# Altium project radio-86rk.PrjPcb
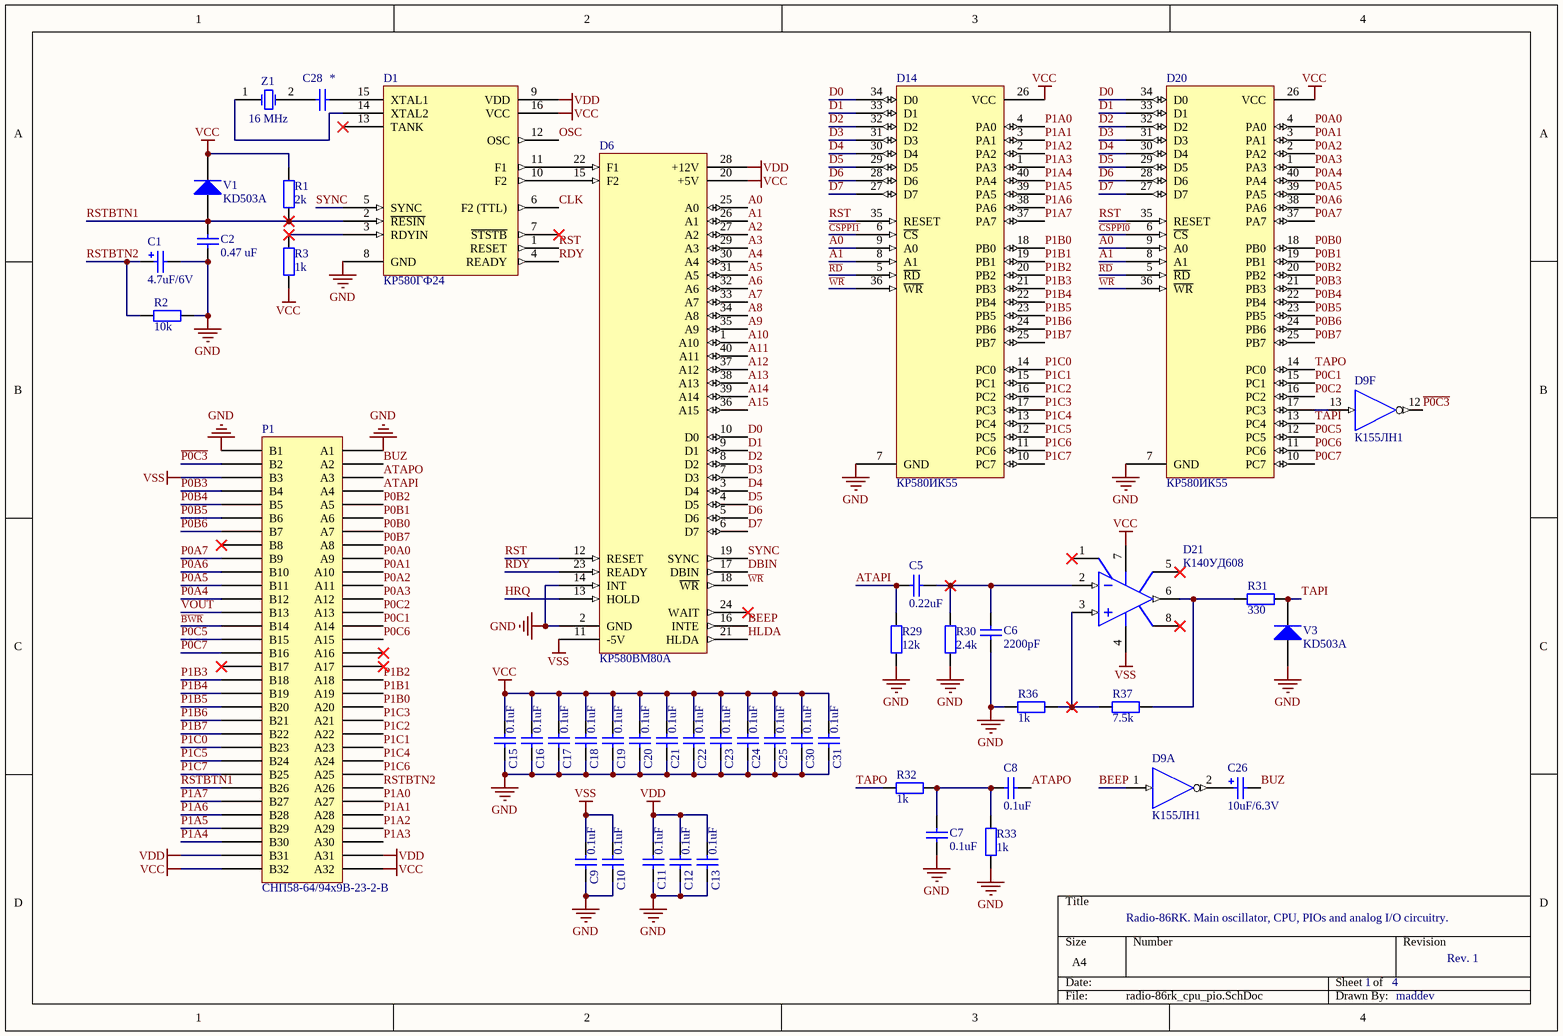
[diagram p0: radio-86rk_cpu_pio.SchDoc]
4 sheets, 104 parts. Net scope: global (net labels, ports and power ports of the same name join across sheets).
Board file: radio-86rk.PcbDoc
Sheets:
  radio-86rk_cpu_pio.SchDoc
  radio-86rk_control.SchDoc
  radio-86rk_rom_ram.SchDoc
  radio-86rk_dma_crt.SchDoc

## Sheet radio-86rk_cpu_pio.SchDoc: Radio-86RK. Main oscillator, CPU, PIOs and analog I/O circuitry.
size A4; DrawnBy: maddev; Revision: Rev. 1; SheetNumber: 1; SheetTotal: 4

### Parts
C1  4.7uF/6V  [CAPPR2.5-6.3x11]
C2  0.47 uF  [CAPR5.08-5.1x2.5]
C5  0.22uF  [CAPR5.08-5.1x2.5]
C6  2200pF  [CAPR5.08-5.1x2.5]
C7  0.1uF  [CAPR5.08-5.1x2.5]
C8  0.1uF  [CAPR5.08-5.1x2.5]
C9  0.1uF  [CAPR5.08-5.1x2.5]
C10  0.1uF  [CAPR5.08-5.1x2.5]
C11  0.1uF  [CAPR5.08-5.1x2.5]
C12  0.1uF  [CAPR5.08-5.1x2.5]
C13  0.1uF  [CAPR5.08-5.1x2.5]
C15  0.1uF  [CAPR5.08-5.1x2.5]
C16  0.1uF  [CAPR5.08-5.1x2.5]
C17  0.1uF  [CAPR5.08-5.1x2.5]
C18  0.1uF  [CAPR5.08-5.1x2.5]
C19  0.1uF  [CAPR5.08-5.1x2.5]
C20  0.1uF  [CAPR5.08-5.1x2.5]
C21  0.1uF  [CAPR5.08-5.1x2.5]
C22  0.1uF  [CAPR5.08-5.1x2.5]
C23  0.1uF  [CAPR5.08-5.1x2.5]
C24  0.1uF  [CAPR5.08-5.1x2.5]
C25  0.1uF  [CAPR5.08-5.1x2.5]
C26  10uF/6.3V  [CAPPR2.5-6.3x11]
C28  *  [CAPR5.08-5.1x2.5]
C30  0.1uF  [CAPR5.08-5.1x2.5]
C31  0.1uF  [CAPR5.08-5.1x2.5]
D1  КР580ГФ24  [DIP16M]
D6  КР580ВМ80А  [DIP40M]
D9  К155ЛН1  [DIP14M]  (parts A,F of 6)
D14  КР580ИК55  [DIP40M]
D20  КР580ИК55  [DIP40M]
D21  К140УД608  [DIP8M]
P1  СНП58-64/94x9В-23-2-В  [snp58]
R1  2k  [AXIAL-0.4]
R2  10k  [AXIAL-0.4]
R3  1k  [AXIAL-0.4]
R29  12k  [AXIAL-0.4]
R30  2.4k  [AXIAL-0.4]
R31  330  [AXIAL-0.4]
R32  1k  [AXIAL-0.4]
R33  1k  [AXIAL-0.4]
R36  1k  [AXIAL-0.4]
R37  7.5k  [AXIAL-0.4]
V1  KD503A  [DO-35A]
V3  KD503A  [DO-35A]
Z1  16 MHz  [HC-49U]

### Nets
GND: C1.2 C2.1 C6.1 C7.1 C9.1 C10.1 C11.1 C12.1 C13.1 C15.1 C16.1 C17.1 C18.1 C19.1 C20.1 C21.1 C22.1 C23.1 C24.1 C25.1 C30.1 C31.1 D1.8(GND) D6.2(GND) D6.14(INT) D9.7(GND) D14.7(GND) D20.7(GND) P1.A1 P1.B1 R2.1 R29.1 R30.1 R33.1 R36.2 V3.1(A)
VCC: C15.2 C16.2 C17.2 C18.2 C19.2 C20.2 C21.2 C22.2 C23.2 C24.2 C25.2 C30.2 C31.2 D1.16(VCC) D6.20(+5V) D9.14(VCC) D14.26(VCC) D20.26(VCC) D21.7(V+) P1.A32 P1.B32 R1.2 R3.1 V1.2(K)
VDD: C11.2 C12.2 C13.2 D1.9(VDD) D6.28(+12V) P1.A31 P1.B31
VSS: C9.2 C10.2 D6.11(-5V) D21.4(V-) P1.B3
A0: D6.25(A0) D14.9(A0) D20.9(A0)
A1: D6.26(A1) D14.8(A1) D20.8(A1)
A2: D6.27(A2)
A3: D6.29(A3)
A4: D6.30(A4)
A5: D6.31(A5)
A6: D6.32(A6)
A7: D6.33(A7)
A8: D6.34(A8)
A9: D6.35(A9)
A10: D6.1(A10)
A11: D6.40(A11)
A12: D6.37(A12)
A13: D6.38(A13)
A14: D6.39(A14)
A15: D6.36(A15)
ATAPI: C5.2 P1.A4 R29.2
ATAPO: C8.1 P1.A3
~{BWR}: P1.B14
BEEP: D6.16(INTE) D9.1(A)
BUZ: C26.2 P1.A2
~{CSPPI0}: D20.6(~{CS})
~{CSPPI1}: D14.6(~{CS})
CLK: D1.6(F2_(TTL))
D0: D6.10(D0) D14.34(D0) D20.34(D0)
D1: D6.9(D1) D14.33(D1) D20.33(D1)
D2: D6.8(D2) D14.32(D2) D20.32(D2)
D3: D6.7(D3) D14.31(D3) D20.31(D3)
D4: D6.3(D4) D14.30(D4) D20.30(D4)
D5: D6.4(D5) D14.29(D5) D20.29(D5)
D6: D6.5(D6) D14.28(D6) D20.28(D6)
D7: D6.6(D7) D14.27(D7) D20.27(D7)
DBIN: D6.17(DBIN)
HLDA: D6.21(HLDA)
HRQ: D6.13(HOLD)
OSC: D1.12(OSC)
P0A0: D20.4(PA0) P1.A9
P0A1: D20.3(PA1) P1.A10
P0A2: D20.2(PA2) P1.A11
P0A3: D20.1(PA3) P1.A12
P0A4: D20.40(PA4) P1.B12
P0A5: D20.39(PA5) P1.B11
P0A6: D20.38(PA6) P1.B10
P0A7: D20.37(PA7) P1.B9
P0B0: D20.18(PB0) P1.A7
P0B1: D20.19(PB1) P1.A6
P0B2: D20.20(PB2) P1.A5
P0B3: D20.21(PB3) P1.B4
P0B4: D20.22(PB4) P1.B5
P0B5: D20.23(PB5) P1.B6
P0B6: D20.24(PB6) P1.B7
P0B7: D20.25(PB7) P1.A8
P0C1: D20.15(PC1) P1.A14
P0C2: D20.16(PC2) P1.A13
P0C5: D20.12(PC5) P1.B15
P0C6: D20.11(PC6) P1.A15
P0C7: D20.10(PC7) P1.B16
P1A0: D14.4(PA0) P1.A27
P1A1: D14.3(PA1) P1.A28
P1A2: D14.2(PA2) P1.A29
P1A3: D14.1(PA3) P1.A30
P1A4: D14.40(PA4) P1.B30
P1A5: D14.39(PA5) P1.B29
P1A6: D14.38(PA6) P1.B28
P1A7: D14.37(PA7) P1.B27
P1B0: D14.18(PB0) P1.A20
P1B1: D14.19(PB1) P1.A19
P1B2: D14.20(PB2) P1.A18
P1B3: D14.21(PB3) P1.B18
P1B4: D14.22(PB4) P1.B19
P1B5: D14.23(PB5) P1.B20
P1B6: D14.24(PB6) P1.B21
P1B7: D14.25(PB7) P1.B22
P1C0: D14.14(PC0) P1.B23
P1C1: D14.15(PC1) P1.A23
P1C2: D14.16(PC2) P1.A22
P1C3: D14.17(PC3) P1.A21
P1C4: D14.13(PC4) P1.A24
P1C5: D14.12(PC5) P1.B24
P1C6: D14.11(PC6) P1.A25
P1C7: D14.10(PC7) P1.B25
~{P0C3}: D9.12(Y) P1.B2
~{RD}: D14.5(~{RD}) D20.5(~{RD})
RDY: D1.4(READY) D6.23(READY)
RST: D1.1(RESET) D6.12(RESET) D14.35(RESET) D20.35(RESET)
RSTBTN1: C2.2 D1.2(~{RESIN}) P1.B26 R1.1 V1.1(A)
RSTBTN2: C1.1 P1.A26 R2.2
SYNC: D1.5(SYNC) D6.19(SYNC)
TAPI: D20.13(PC4) R31.2 V3.2(K)
TAPO: D20.14(PC0) R32.1
VOUT: P1.B13
~{WR}: D6.18(~{WR}) D14.36(~{WR}) D20.36(~{WR})
NetC5_1: C5.1 C6.2 D21.2(IN-) R30.2
NetC7_2: C7.2 C8.2 R32.2 R33.2
NetC26_1: C26.1 D9.2(Y)
NetC28_1: C28.1 D1.15(XTAL1)
NetC28_2: C28.2 Z1.2(OSC2)
NetD1_3: D1.3(RDYIN) R3.2
NetD1_10: D1.10(F2) D6.15(F2)
NetD1_11: D1.11(F1) D6.22(F1)
NetD1_14: D1.14(XTAL2) Z1.1(OSC1)
NetD9_13: D9.13(A) D20.17(PC3)
NetD21_3: D21.3(IN+) R36.1 R37.2
NetD21_6: D21.6(OUT) R31.1 R37.1

Not connected (* = marked no-connect by the designer): D1 7(~{STSTB})* 13(TANK)*; D6 24(WAIT)*; D21 1(OS_NULL)* 5(OS_NULL)* 8(NC)*; P1 A16* A17* B8* B17*

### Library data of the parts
C1 = Cap Pol2: Polarized Capacitor (Axial); AltValue: 10uF/6.3V
C2 = Cap: Capacitor; AltValue: 1uF
C5-C13 C15-C25 C30 C31 = Cap: Capacitor; Value: 100pF
C26 = Cap Pol2: Polarized Capacitor (Axial); Value: 100pF
C28 = Cap: Capacitor; AltValue: JUMPER
D1 = КР580ГФ24: Clock generator and driver for 8080A CPU
D6 = КР580ВМ80А: 8-bit N-channel microprocessor
D9 = SN7404N: Hex Inverter
D14 D20 = КР580ИК55: Programmable peripheral interface
D21 = MC1456P1: High-Performance Operational Amplifier
R1 = Res2: Resistor; AltValue: 1k
R2 R29-R31 R37 = Res2: Resistor; Value: 1K
R3 R32 R33 R36 = Res2: Resistor
V1 V3 = Diode 1N4149: Computer Diode
Z1 = XTAL: Crystal Oscillator

## Sheet radio-86rk_control.SchDoc: Radio-86RK. Address decoding and DRAM control.
size A4; DrawnBy: maddev; Revision: Rev. 1; SheetNumber: 2; SheetTotal: 4
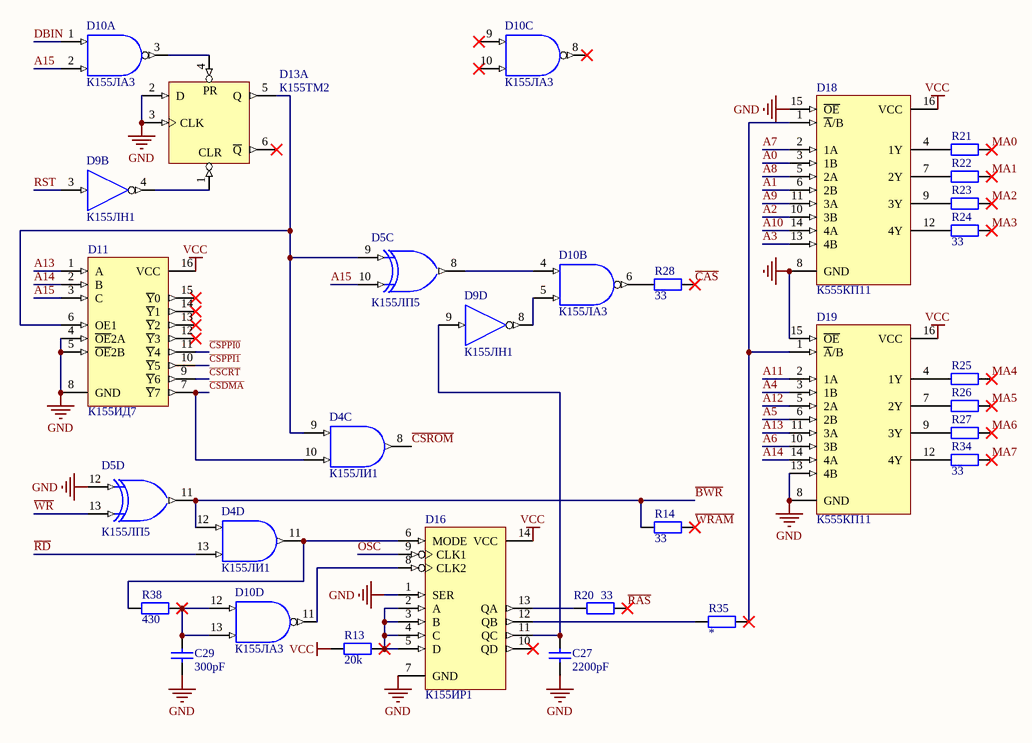
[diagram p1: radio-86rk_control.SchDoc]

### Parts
C27  2200pF  [CAPR5.08-5.1x2.5]
C29  300pF  [CAPR5.08-5.1x2.5]
D4  К155ЛИ1  [DIP14M]  (parts C,D of 4)
D5  К155ЛП5  [DIP14M]  (parts C,D of 4)
D9  К155ЛН1  [DIP14M]  (parts B,D of 6)
D10  К155ЛА3  [DIP14M]  (parts A,B,C,D of 4)
D11  К155ИД7  [DIP16M]
D13  К155ТМ2  [DIP14M]  (part A of 2)
D16  К155ИР1  [DIP14M]
D18  К555КП11  [DIP16M]
D19  К555КП11  [DIP16M]
R13  20k  [AXIAL-0.4]
R14  33  [AXIAL-0.4]
R20  33  [AXIAL-0.4]
R21  33  [AXIAL-0.4]  (value not drawn)
R22  33  [AXIAL-0.4]  (value not drawn)
R23  33  [AXIAL-0.4]  (value not drawn)
R24  33  [AXIAL-0.4]
R25  33  [AXIAL-0.4]  (value not drawn)
R26  33  [AXIAL-0.4]  (value not drawn)
R27  33  [AXIAL-0.4]  (value not drawn)
R28  33  [AXIAL-0.4]
R34  33  [AXIAL-0.4]
R35  *  [AXIAL-0.4]
R38  430  [AXIAL-0.4]

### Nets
GND: C27.2 C29.2 D4.7(GND) D5.7(GND) D5.12(A) D9.7(GND) D10.7(GND) D11.4(~{OE}2A) D11.5(~{OE}2B) D11.8(GND) D13.2(D) D13.3(CLK) D13.7(GND) D16.1(SER) D16.7(GND) D18.8(GND) D18.15(~{OE}) D19.8(GND) D19.13(4B) D19.15(~{OE})
VCC: D4.14(VCC) D5.14(VCC) D9.14(VCC) D10.14(VCC) D11.16(VCC) D13.14(VCC) D16.14(VCC) D18.16(VCC) D19.16(VCC) R13.1
A0: D18.3(1B)
A1: D18.6(2B)
A2: D18.10(3B)
A3: D18.13(4B)
A4: D19.3(1B)
A5: D19.6(2B)
A6: D19.10(3B)
A7: D18.2(1A)
A8: D18.5(2A)
A9: D18.11(3A)
A10: D18.14(4A)
A11: D19.2(1A)
A12: D19.5(2A)
A13: D11.1(A) D19.11(3A)
A14: D11.2(B) D19.14(4A)
A15: D5.10(B) D10.2(B) D11.3(C)
~{BWR}: D4.12(A) D5.11(Y) R14.2
~{CAS}: R28.1
~{CSCRT}: D11.9(~{Y}6)
~{CSDMA}: D4.10(B) D11.7(~{Y}7)
~{CSPPI0}: D11.11(~{Y}4)
~{CSPPI1}: D11.10(~{Y}5)
~{CSROM}: D4.8(Y)
DBIN: D10.1(A)
MA0: R21.1
MA1: R22.1
MA2: R23.1
MA3: R24.1
MA4: R25.1
MA5: R26.1
MA6: R27.1
MA7: R34.1
OSC: D16.9(CLK1)
~{RAS}: R20.1
~{RD}: D4.13(B)
RST: D9.3(A)
~{WR}: D5.13(B)
~{WRAM}: R14.1
NetC27_1: C27.1 D9.9(A) D16.11(QC)
NetC29_1: C29.1 D10.12(A) D10.13(B) R38.2
NetD4_9: D4.9(A) D5.9(A) D11.6(OE1) D13.5(Q)
NetD4_11: D4.11(Y) D16.6(MODE) R38.1
NetD5_8: D5.8(Y) D10.4(A)
NetD9_4: D9.4(Y) D13.1(CLR)
NetD9_8: D9.8(Y) D10.5(B)
NetD10_3: D10.3(Y) D13.4(PR)
NetD10_6: D10.6(Y) R28.2
NetD10_11: D10.11(Y) D16.8(CLK2)
NetD16_2: D16.2(A) D16.3(B) D16.4(C) D16.5(D) R13.2
NetD16_12: D16.12(QB) R35.2
NetD16_13: D16.13(QA) R20.2
NetD18_1: D18.1(~{A}/B) D19.1(~{A}/B) R35.1
NetD18_4: D18.4(1Y) R21.2
NetD18_7: D18.7(2Y) R22.2
NetD18_9: D18.9(3Y) R23.2
NetD18_12: D18.12(4Y) R24.2
NetD19_4: D19.4(1Y) R25.2
NetD19_7: D19.7(2Y) R26.2
NetD19_9: D19.9(3Y) R27.2
NetD19_12: D19.12(4Y) R34.2

Not connected (* = marked no-connect by the designer): D10 8(Y)* 9(A)* 10(B)*; D11 12(~{Y}3)* 13(~{Y}2)* 14(~{Y}1)* 15(~{Y}0)*; D13 6(~{Q})*; D16 10(QD)*

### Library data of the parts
C27 = Cap: Capacitor
C29 = Cap: Capacitor; AltValue: JUMPER
D4 = SN7408N: Quadruple 2-Input Positive-AND Gate
D5 = SN7486N: Quadruple 2-Input Exclusive-OR Gate
D9 = SN7404N: Hex Inverter
D10 = SN7400N: Quadruple 2-Input Positive-NAND Gate
D11 = SN74LS138N: 3-Line to 8-Line Decoder / Demultiplexer
D13 = SN7474N: Dual D-Type Positive-Edge-Triggered Flip-Flop with Preset and Clear; ComponentAvailability: Obsolete
D16 = SN7495AN: 4-Bit Parallel-Access Shift Register; ComponentAvailability: Obsolete
D18 D19 = SN74LS257BN: Quadruple 2-Line to 1-Line Data Selector/Multiplexer with 3-State Outputs
R13 = Res2: Resistor; AltValue: 10k
R14 R20-R28 R34 = Res2: Resistor; Value: 1K
R35 = Res2: Resistor; AltValue: JUMPER
R38 = Res2: Resistor

## Sheet radio-86rk_rom_ram.SchDoc: Radio-86RK. ROM and RAM.
size A4; DrawnBy: maddev; Revision: Rev. 1; SheetNumber: 3; SheetTotal: 4
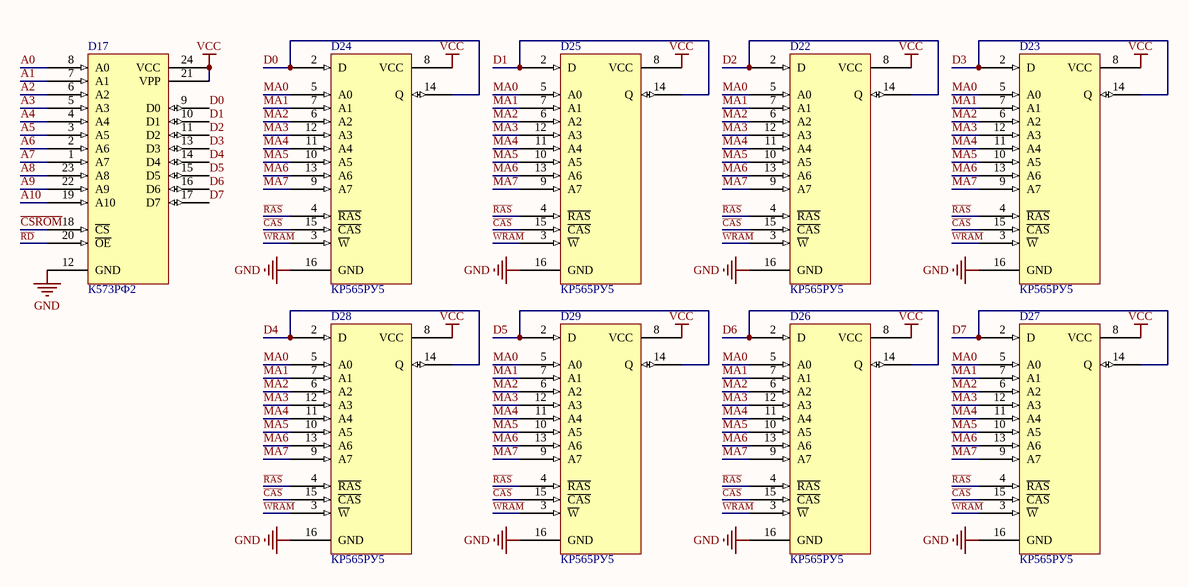
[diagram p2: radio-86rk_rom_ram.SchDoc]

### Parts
D17  К573РФ2  [DIP24M]
D22  КР565РУ5  [DIP16M]
D23  КР565РУ5  [DIP16M]
D24  КР565РУ5  [DIP16M]
D25  КР565РУ5  [DIP16M]
D26  КР565РУ5  [DIP16M]
D27  КР565РУ5  [DIP16M]
D28  КР565РУ5  [DIP16M]
D29  КР565РУ5  [DIP16M]

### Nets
GND: D17.12(GND) D22.16(GND) D23.16(GND) D24.16(GND) D25.16(GND) D26.16(GND) D27.16(GND) D28.16(GND) D29.16(GND)
VCC: D17.21(VPP) D17.24(VCC) D22.8(VCC) D23.8(VCC) D24.8(VCC) D25.8(VCC) D26.8(VCC) D27.8(VCC) D28.8(VCC) D29.8(VCC)
A0: D17.8(A0)
A1: D17.7(A1)
A2: D17.6(A2)
A3: D17.5(A3)
A4: D17.4(A4)
A5: D17.3(A5)
A6: D17.2(A6)
A7: D17.1(A7)
A8: D17.23(A8)
A9: D17.22(A9)
A10: D17.19(A10)
~{CAS}: D22.15(~{CAS}) D23.15(~{CAS}) D24.15(~{CAS}) D25.15(~{CAS}) D26.15(~{CAS}) D27.15(~{CAS}) D28.15(~{CAS}) D29.15(~{CAS})
~{CSROM}: D17.18(~{CS})
D0: D17.9(D0) D24.2(D) D24.14(Q)
D1: D17.10(D1) D25.2(D) D25.14(Q)
D2: D17.11(D2) D22.2(D) D22.14(Q)
D3: D17.13(D3) D23.2(D) D23.14(Q)
D4: D17.14(D4) D28.2(D) D28.14(Q)
D5: D17.15(D5) D29.2(D) D29.14(Q)
D6: D17.16(D6) D26.2(D) D26.14(Q)
D7: D17.17(D7) D27.2(D) D27.14(Q)
MA0: D22.5(A0) D23.5(A0) D24.5(A0) D25.5(A0) D26.5(A0) D27.5(A0) D28.5(A0) D29.5(A0)
MA1: D22.7(A1) D23.7(A1) D24.7(A1) D25.7(A1) D26.7(A1) D27.7(A1) D28.7(A1) D29.7(A1)
MA2: D22.6(A2) D23.6(A2) D24.6(A2) D25.6(A2) D26.6(A2) D27.6(A2) D28.6(A2) D29.6(A2)
MA3: D22.12(A3) D23.12(A3) D24.12(A3) D25.12(A3) D26.12(A3) D27.12(A3) D28.12(A3) D29.12(A3)
MA4: D22.11(A4) D23.11(A4) D24.11(A4) D25.11(A4) D26.11(A4) D27.11(A4) D28.11(A4) D29.11(A4)
MA5: D22.10(A5) D23.10(A5) D24.10(A5) D25.10(A5) D26.10(A5) D27.10(A5) D28.10(A5) D29.10(A5)
MA6: D22.13(A6) D23.13(A6) D24.13(A6) D25.13(A6) D26.13(A6) D27.13(A6) D28.13(A6) D29.13(A6)
MA7: D22.9(A7) D23.9(A7) D24.9(A7) D25.9(A7) D26.9(A7) D27.9(A7) D28.9(A7) D29.9(A7)
~{RAS}: D22.4(~{RAS}) D23.4(~{RAS}) D24.4(~{RAS}) D25.4(~{RAS}) D26.4(~{RAS}) D27.4(~{RAS}) D28.4(~{RAS}) D29.4(~{RAS})
~{RD}: D17.20(~{OE})
~{WRAM}: D22.3(~{W}) D23.3(~{W}) D24.3(~{W}) D25.3(~{W}) D26.3(~{W}) D27.3(~{W}) D28.3(~{W}) D29.3(~{W})

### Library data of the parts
D22-D29 = 4164: 64K X 1 bit dynamic RAM

## Sheet radio-86rk_dma_crt.SchDoc: Radio-86RK. DMA, CRT and analog video circuitry.
size A4; DrawnBy: maddev; Revision: Rev. 1; SheetNumber: 4; SheetTotal: 4
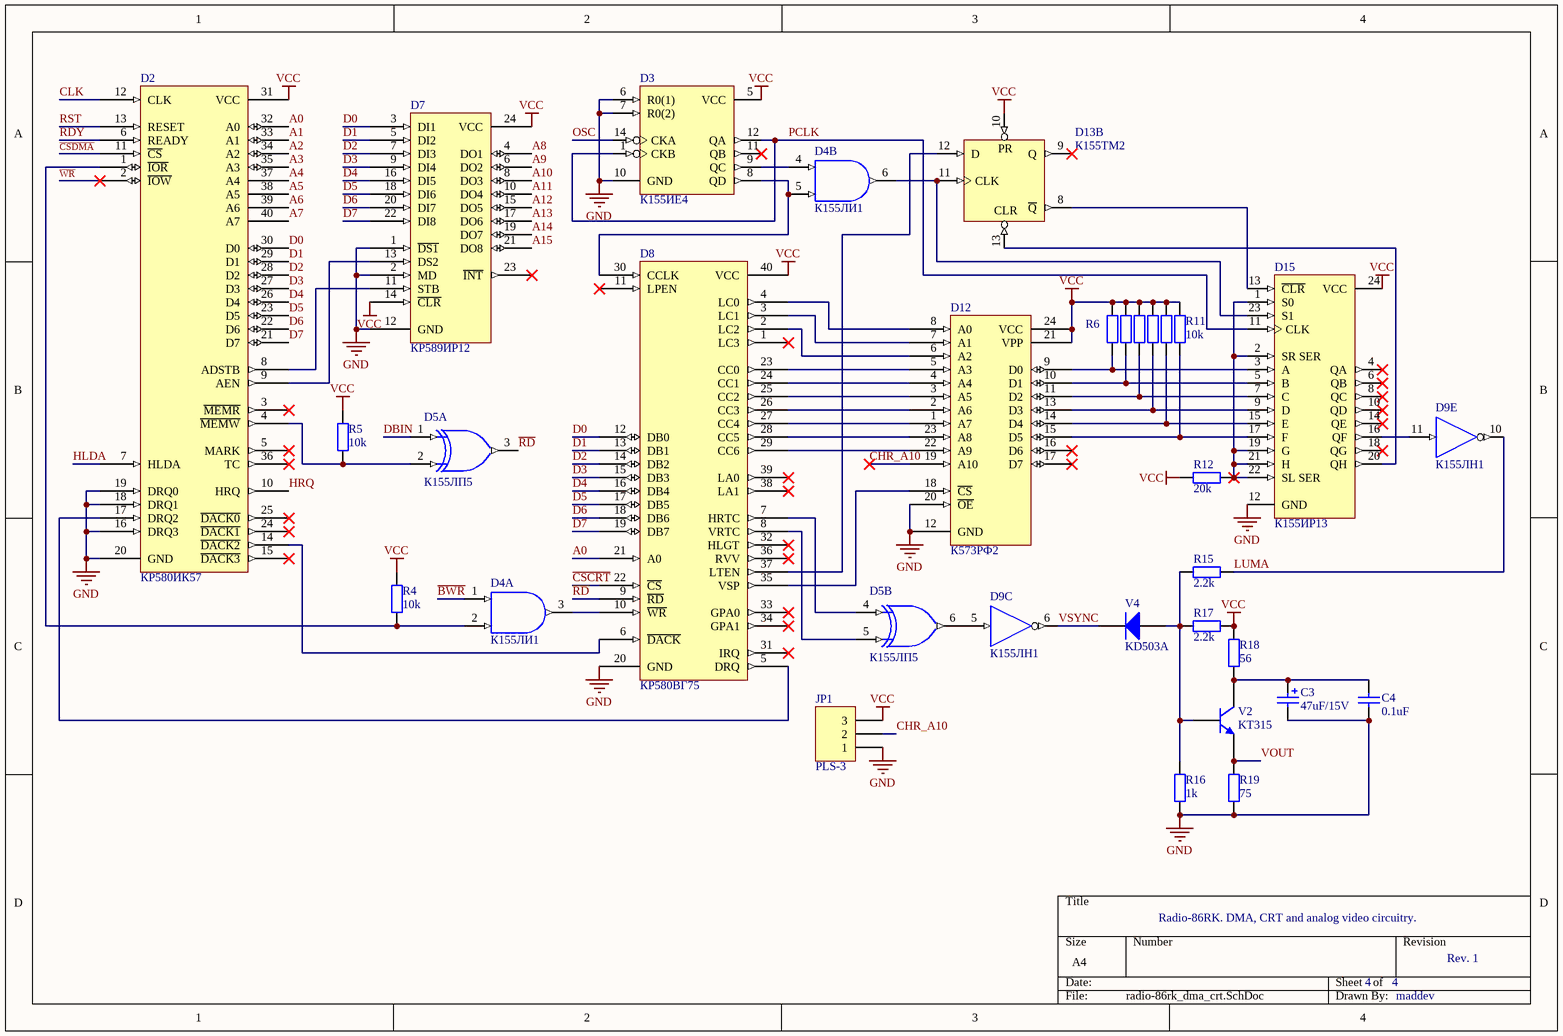
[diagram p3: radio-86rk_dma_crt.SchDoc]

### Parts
C3  47uF/15V  [CAPPR2.5-6.3x11]
C4  0.1uF  [CAPR5.08-5.1x2.5]
D2  КР580ИК57  [DIP40M]
D3  К155ИЕ4  [DIP14M]
D4  К155ЛИ1  [DIP14M]  (parts A,B of 4)
D5  К155ЛП5  [DIP14M]  (parts A,B of 4)
D7  КР589ИР12  [DIP24M]
D8  КР580ВГ75  [DIP40M]
D9  К155ЛН1  [DIP14M]  (parts C,E of 6)
D12  К573РФ2  [DIP24M]
D13  К155ТМ2  [DIP14M]  (part B of 2)
D15  К155ИР13  [DIP24M]
JP1  PLS-3  [HDR1X3]
R4  10k  [AXIAL-0.4]
R5  10k  [AXIAL-0.4]
R6  10k  [AXIAL-0.4]  (value not drawn)
R7  10k  [AXIAL-0.4]  (value not drawn)
R8  10k  [AXIAL-0.4]  (value not drawn)
R9  10k  [AXIAL-0.4]  (value not drawn)
R10  10k  [AXIAL-0.4]  (value not drawn)
R11  10k  [AXIAL-0.4]
R12  20k  [AXIAL-0.4]
R15  2.2k  [AXIAL-0.4]
R16  1k  [AXIAL-0.4]
R17  2.2k  [AXIAL-0.4]
R18  56  [AXIAL-0.4]
R19  75  [AXIAL-0.4]
V2  KT315  [KT315]
V4  KD503A  [DO-35A]

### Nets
GND: C3.2 C4.1 D2.16(DRQ3) D2.18(DRQ1) D2.19(DRQ0) D2.20(GND) D3.6(R0(1)) D3.7(R0(2)) D3.10(GND) D4.7(GND) D5.7(GND) D7.1(~{DS1}) D7.2(MD) D7.12(GND) D8.20(GND) D9.7(GND) D12.12(GND) D12.20(~{OE}) D13.7(GND) D15.12(GND) JP1.1 R16.1 R19.1
VCC: D2.31(VCC) D3.5(VCC) D4.14(VCC) D5.14(VCC) D7.14(~{CLR}) D7.24(VCC) D8.40(VCC) D9.14(VCC) D12.21(VPP) D12.24(VCC) D13.10(PR) D13.14(VCC) D15.24(VCC) JP1.3 R4.1 R5.1 R6.2 R7.2 R8.2 R9.2 R10.2 R11.2 R12.2 R17.2 R18.1
A0: D2.32(A0) D8.21(A0)
A1: D2.33(A1)
A2: D2.34(A2)
A3: D2.35(A3)
A4: D2.37(A4)
A5: D2.38(A5)
A6: D2.39(A6)
A7: D2.40(A7)
A8: D7.4(DO1)
A9: D7.6(DO2)
A10: D7.8(DO3)
A11: D7.10(DO4)
A12: D7.15(DO5)
A13: D7.17(DO6)
A14: D7.19(DO7)
A15: D7.21(DO8)
~{BWR}: D4.1(A)
~{CSCRT}: D8.22(~{CS})
~{CSDMA}: D2.11(~{CS})
CHR_A10: D12.19(A10) JP1.2
CLK: D2.12(CLK)
D0: D2.30(D0) D7.3(DI1) D8.12(DB0)
D1: D2.29(D1) D7.5(DI2) D8.13(DB1)
D2: D2.28(D2) D7.7(DI3) D8.14(DB2)
D3: D2.27(D3) D7.9(DI4) D8.15(DB3)
D4: D2.26(D4) D7.16(DI5) D8.16(DB4)
D5: D2.23(D5) D7.18(DI6) D8.17(DB5)
D6: D2.22(D6) D7.20(DI7) D8.18(DB6)
D7: D2.21(D7) D7.22(DI8) D8.19(DB7)
DBIN: D5.1(A)
HLDA: D2.7(HLDA)
HRQ: D2.10(HRQ)
LUMA: D9.10(Y) R15.1
OSC: D3.14(CKA)
PCLK: D3.1(CKB) D3.12(QA) D15.11(CLK)
~{RD}: D5.3(Y) D8.9(~{RD})
RDY: D2.6(READY)
RST: D2.13(RESET)
VOUT: R19.2 V2.3(E)
VSYNC: D9.6(Y) V4.2(K)
~{WR}: D2.2(~{IOW})
NetC3_1: C3.1 C4.2 R18.2 V2.1(C)
NetD2_1: D2.1(~{IOR}) D4.2(B) R4.2
NetD2_4: D2.4(~{MEMW}) D5.2(B) R5.2
NetD2_8: D2.8(ADSTB) D7.11(STB)
NetD2_9: D2.9(AEN) D7.13(DS2)
NetD2_14: D2.14(~{DACK2}) D8.6(~{DACK})
NetD2_17: D2.17(DRQ2) D8.5(DRQ)
NetD3_8: D3.8(QD) D4.5(B) D8.30(CCLK)
NetD3_9: D3.9(QC) D4.4(A)
NetD4_3: D4.3(Y) D8.10(~{WR})
NetD4_6: D4.6(Y) D13.11(CLK) D15.23(S1)
NetD5_4: D5.4(A) D8.7(HRTC)
NetD5_5: D5.5(B) D8.8(VRTC)
NetD5_6: D5.6(Y) D9.5(A)
NetD8_2: D8.2(LC2) D12.6(A2)
NetD8_3: D8.3(LC1) D12.7(A1)
NetD8_4: D8.4(LC0) D12.8(A0)
NetD8_23: D8.23(CC0) D12.5(A3)
NetD8_24: D8.24(CC1) D12.4(A4)
NetD8_25: D8.25(CC2) D12.3(A5)
NetD8_26: D8.26(CC3) D12.2(A6)
NetD8_27: D8.27(CC4) D12.1(A7)
NetD8_28: D8.28(CC5) D12.23(A8)
NetD8_29: D8.29(CC6) D12.22(A9)
NetD8_35: D8.35(VSP) D12.18(~{CS})
NetD8_37: D8.37(LTEN) D13.12(D)
NetD9_11: D9.11(A) D15.16(QF)
NetD12_9: D12.9(D0) D15.3(A) R6.1
NetD12_10: D12.10(D1) D15.5(B) R7.1
NetD12_11: D12.11(D2) D15.7(C) R8.1
NetD12_13: D12.13(D3) D15.9(D) R9.1
NetD12_14: D12.14(D4) D15.15(E) R10.1
NetD12_15: D12.15(D5) D15.17(F) R11.1
NetD13_8: D13.8(~{Q}) D15.13(~{CLR})
NetD13_13: D13.13(CLR) D15.20(QH)
NetD15_1: D15.1(S0) D15.2(SR_SER) D15.19(G) D15.21(H) D15.22(SL_SER) R12.1
NetR15_2: R15.2 R16.2 R17.1 V2.2(B) V4.1(A)

Not connected (* = marked no-connect by the designer): D2 3(~{MEMR})* 5(MARK)* 15(~{DACK3})* 24(~{DACK1})* 25(~{DACK0})* 36(TC)*; D3 11(QB)*; D7 23(~{INT})*; D8 1(LC3)* 11(LPEN)* 31(IRQ)* 32(HLGT)* 33(GPA0)* 34(GPA1)* 36(RVV)* 38(LA1)* 39(LA0)*; D12 16(D6)* 17(D7)*; D13 9(Q)*; D15 4(QA)* 6(QB)* 8(QC)* 10(QD)* 14(QE)* 18(QG)*

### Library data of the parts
C3 = Cap Pol2: Polarized Capacitor (Axial); AltValue: 100uF/6.3V
C4 = Cap: Capacitor; Value: 100pF
D2 = КР580ИК57: Programmable DMA controller
D3 = SN7492AN: Divide-by-Twelve Counter; Note: Pins 2, 3, 4 and 13 - no connection and not drawn.; ComponentAvailability: Obsolete
D4 = SN7408N: Quadruple 2-Input Positive-AND Gate
D5 = SN7486N: Quadruple 2-Input Exclusive-OR Gate
D7 = 8212: 8-bit input/output port
D8 = КР580ВГ75: Programmable CRT controller
D9 = SN7404N: Hex Inverter
D13 = SN7474N: as D13 on sheet radio-86rk_control
D15 = SN74198N: 8-Bit Shift Register; ComponentAvailability: Obsolete
JP1 = Header 3: Header, 3-Pin
R4-R11 R15 R17-R19 = Res2: Resistor; Value: 1K
R12 = Res2: Resistor; AltValue: 10k
R16 = Res2: Resistor
V2 = NPN: NPN Bipolar Transistor; pin to pad: 1>C 2>B 3>E
V4 = Diode 1N4149: Computer Diode

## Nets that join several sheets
GND: radio-86rk_cpu_pio (36 pins), radio-86rk_control (20 pins), radio-86rk_rom_ram (9 pins), radio-86rk_dma_crt (23 pins)
VCC: radio-86rk_cpu_pio (24 pins), radio-86rk_control (10 pins), radio-86rk_rom_ram (10 pins), radio-86rk_dma_crt (25 pins)
A0: radio-86rk_cpu_pio (D6.25 D14.9 D20.9), radio-86rk_control (D18.3), radio-86rk_rom_ram (D17.8), radio-86rk_dma_crt (D2.32 D8.21)
A1: radio-86rk_cpu_pio (D6.26 D14.8 D20.8), radio-86rk_control (D18.6), radio-86rk_rom_ram (D17.7), radio-86rk_dma_crt (D2.33)
A2: radio-86rk_cpu_pio (D6.27), radio-86rk_control (D18.10), radio-86rk_rom_ram (D17.6), radio-86rk_dma_crt (D2.34)
A3: radio-86rk_cpu_pio (D6.29), radio-86rk_control (D18.13), radio-86rk_rom_ram (D17.5), radio-86rk_dma_crt (D2.35)
A4: radio-86rk_cpu_pio (D6.30), radio-86rk_control (D19.3), radio-86rk_rom_ram (D17.4), radio-86rk_dma_crt (D2.37)
A5: radio-86rk_cpu_pio (D6.31), radio-86rk_control (D19.6), radio-86rk_rom_ram (D17.3), radio-86rk_dma_crt (D2.38)
A6: radio-86rk_cpu_pio (D6.32), radio-86rk_control (D19.10), radio-86rk_rom_ram (D17.2), radio-86rk_dma_crt (D2.39)
A7: radio-86rk_cpu_pio (D6.33), radio-86rk_control (D18.2), radio-86rk_rom_ram (D17.1), radio-86rk_dma_crt (D2.40)
A8: radio-86rk_cpu_pio (D6.34), radio-86rk_control (D18.5), radio-86rk_rom_ram (D17.23), radio-86rk_dma_crt (D7.4)
A9: radio-86rk_cpu_pio (D6.35), radio-86rk_control (D18.11), radio-86rk_rom_ram (D17.22), radio-86rk_dma_crt (D7.6)
A10: radio-86rk_cpu_pio (D6.1), radio-86rk_control (D18.14), radio-86rk_rom_ram (D17.19), radio-86rk_dma_crt (D7.8)
A11: radio-86rk_cpu_pio (D6.40), radio-86rk_control (D19.2), radio-86rk_dma_crt (D7.10)
A12: radio-86rk_cpu_pio (D6.37), radio-86rk_control (D19.5), radio-86rk_dma_crt (D7.15)
A13: radio-86rk_cpu_pio (D6.38), radio-86rk_control (D11.1 D19.11), radio-86rk_dma_crt (D7.17)
A14: radio-86rk_cpu_pio (D6.39), radio-86rk_control (D11.2 D19.14), radio-86rk_dma_crt (D7.19)
A15: radio-86rk_cpu_pio (D6.36), radio-86rk_control (D5.10 D10.2 D11.3), radio-86rk_dma_crt (D7.21)
~{BWR}: radio-86rk_cpu_pio (P1.B14), radio-86rk_control (D4.12 D5.11 R14.2), radio-86rk_dma_crt (D4.1)
~{CAS}: radio-86rk_control (R28.1), radio-86rk_rom_ram (8 pins)
~{CSCRT}: radio-86rk_control (D11.9), radio-86rk_dma_crt (D8.22)
~{CSDMA}: radio-86rk_control (D4.10 D11.7), radio-86rk_dma_crt (D2.11)
~{CSPPI0}: radio-86rk_cpu_pio (D20.6), radio-86rk_control (D11.11)
~{CSPPI1}: radio-86rk_cpu_pio (D14.6), radio-86rk_control (D11.10)
~{CSROM}: radio-86rk_control (D4.8), radio-86rk_rom_ram (D17.18)
CLK: radio-86rk_cpu_pio (D1.6), radio-86rk_dma_crt (D2.12)
D0: radio-86rk_cpu_pio (D6.10 D14.34 D20.34), radio-86rk_rom_ram (D17.9 D24.2 D24.14), radio-86rk_dma_crt (D2.30 D7.3 D8.12)
D1: radio-86rk_cpu_pio (D6.9 D14.33 D20.33), radio-86rk_rom_ram (D17.10 D25.2 D25.14), radio-86rk_dma_crt (D2.29 D7.5 D8.13)
D2: radio-86rk_cpu_pio (D6.8 D14.32 D20.32), radio-86rk_rom_ram (D17.11 D22.2 D22.14), radio-86rk_dma_crt (D2.28 D7.7 D8.14)
D3: radio-86rk_cpu_pio (D6.7 D14.31 D20.31), radio-86rk_rom_ram (D17.13 D23.2 D23.14), radio-86rk_dma_crt (D2.27 D7.9 D8.15)
D4: radio-86rk_cpu_pio (D6.3 D14.30 D20.30), radio-86rk_rom_ram (D17.14 D28.2 D28.14), radio-86rk_dma_crt (D2.26 D7.16 D8.16)
D5: radio-86rk_cpu_pio (D6.4 D14.29 D20.29), radio-86rk_rom_ram (D17.15 D29.2 D29.14), radio-86rk_dma_crt (D2.23 D7.18 D8.17)
D6: radio-86rk_cpu_pio (D6.5 D14.28 D20.28), radio-86rk_rom_ram (D17.16 D26.2 D26.14), radio-86rk_dma_crt (D2.22 D7.20 D8.18)
D7: radio-86rk_cpu_pio (D6.6 D14.27 D20.27), radio-86rk_rom_ram (D17.17 D27.2 D27.14), radio-86rk_dma_crt (D2.21 D7.22 D8.19)
DBIN: radio-86rk_cpu_pio (D6.17), radio-86rk_control (D10.1), radio-86rk_dma_crt (D5.1)
HLDA: radio-86rk_cpu_pio (D6.21), radio-86rk_dma_crt (D2.7)
HRQ: radio-86rk_cpu_pio (D6.13), radio-86rk_dma_crt (D2.10)
MA0: radio-86rk_control (R21.1), radio-86rk_rom_ram (8 pins)
MA1: radio-86rk_control (R22.1), radio-86rk_rom_ram (8 pins)
MA2: radio-86rk_control (R23.1), radio-86rk_rom_ram (8 pins)
MA3: radio-86rk_control (R24.1), radio-86rk_rom_ram (8 pins)
MA4: radio-86rk_control (R25.1), radio-86rk_rom_ram (8 pins)
MA5: radio-86rk_control (R26.1), radio-86rk_rom_ram (8 pins)
MA6: radio-86rk_control (R27.1), radio-86rk_rom_ram (8 pins)
MA7: radio-86rk_control (R34.1), radio-86rk_rom_ram (8 pins)
OSC: radio-86rk_cpu_pio (D1.12), radio-86rk_control (D16.9), radio-86rk_dma_crt (D3.14)
~{RAS}: radio-86rk_control (R20.1), radio-86rk_rom_ram (8 pins)
~{RD}: radio-86rk_cpu_pio (D14.5 D20.5), radio-86rk_control (D4.13), radio-86rk_rom_ram (D17.20), radio-86rk_dma_crt (D5.3 D8.9)
RDY: radio-86rk_cpu_pio (D1.4 D6.23), radio-86rk_dma_crt (D2.6)
RST: radio-86rk_cpu_pio (D1.1 D6.12 D14.35 D20.35), radio-86rk_control (D9.3), radio-86rk_dma_crt (D2.13)
VOUT: radio-86rk_cpu_pio (P1.B13), radio-86rk_dma_crt (R19.2 V2.3)
~{WR}: radio-86rk_cpu_pio (D6.18 D14.36 D20.36), radio-86rk_control (D5.13), radio-86rk_dma_crt (D2.2)
~{WRAM}: radio-86rk_control (R14.1), radio-86rk_rom_ram (8 pins)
